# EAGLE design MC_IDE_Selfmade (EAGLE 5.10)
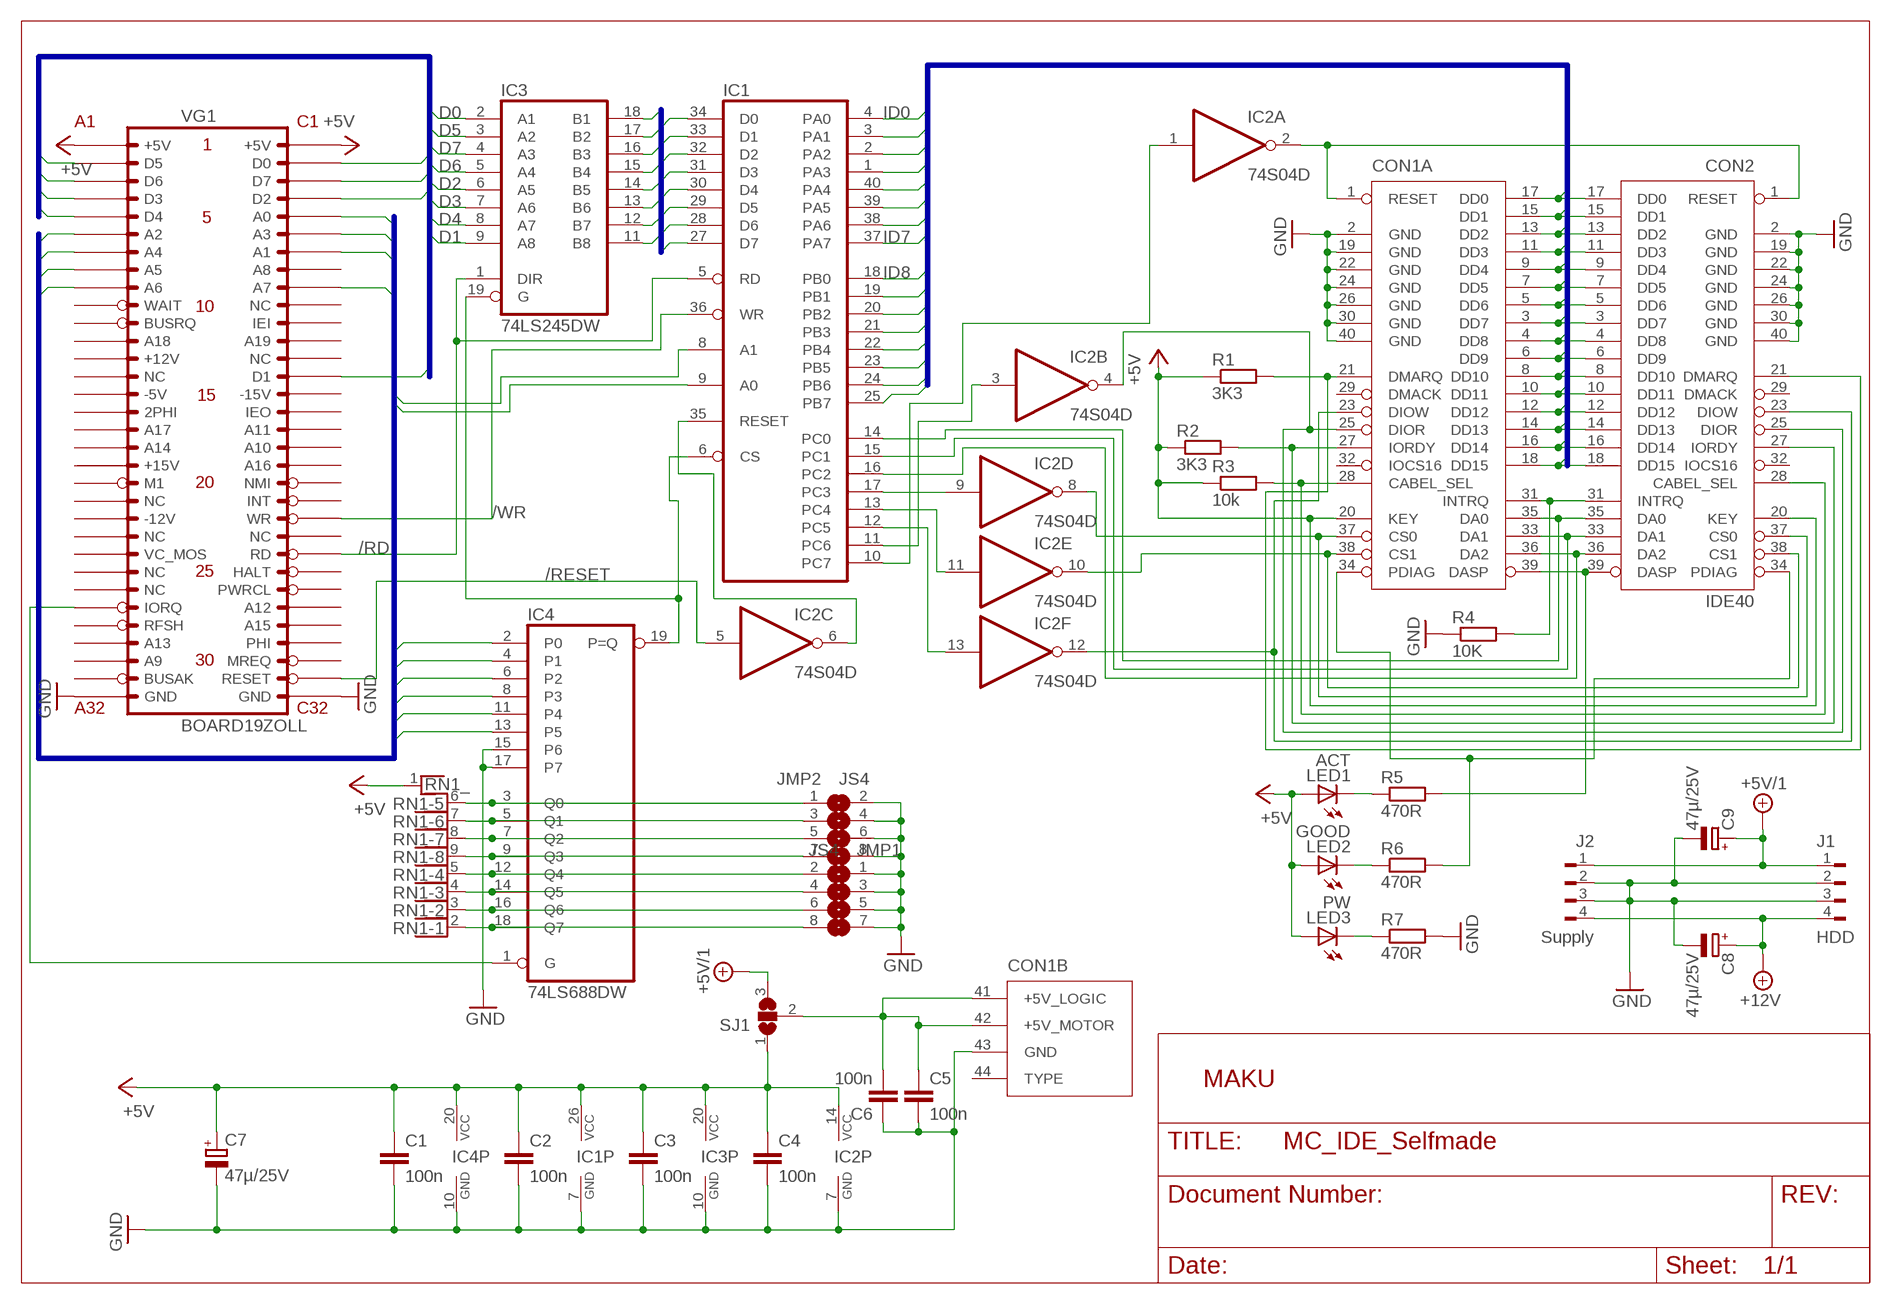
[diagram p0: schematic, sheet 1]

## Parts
C1  100n  C-EU050-025X075  [C050-025X075]
C2  100n  C-EU050-025X075  [C050-025X075]
C3  100n  C-EU050-025X075  [C050-025X075]
C4  100n  C-EU050-025X075  [C050-025X075]
C5  100n  C-EUC1210K  [C1210K]
C6  100n  C-EUC1210K  [C1210K]
C7  47µ/25V  CPOL-EUE2-5  [E2-5]
C8  47µ/25V  CPOL-EUE2-5  [E2-5]
C9  47µ/25V  CPOL-EUE2-5  [E2-5]
CON1  IDE_442,5"  [IDE_44]
CON2  IDE40  IDE_40  [ML40]
IC1  8255A  [DIL40]
IC2  74S04D  [SO14]
IC3  74LS245DW  [SO20W]
IC4  74LS688DW  [SO20W]
J1  HDD  FLOPPY-4350211  [350211]
J2  Supply  FLOPPY-4350211  [350211]
JMP1  JS4  [SJ4]
JMP2  JS4  [SJ4]
LED1  ACT  LED3MM  [LED3MM]
LED2  GOOD  LED3MM  [LED3MM]
LED3  PW  LED3MM  [LED3MM]
R1  3K3  R-EU_0207/10  [0207/10]
R2  3K3  R-EU_0207/10  [0207/10]
R3  10k  R-EU_0207/10  [0207/10]
R4  10K  R-EU_0207/10  [0207/10]
R5  470R  R-EU_0207/10  [0207/10]
R6  470R  R-EU_0207/10  [0207/10]
R7  470R  R-EU_0207/10  [0207/10]
RN1  RNX8  [RN-9]
SJ1  SJ2W  [SJ_2]
VG1  BOARD19ZOLL  [BOARD19S]

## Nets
+5V: C1.1 C2.1 C3.1 C4.1 C7.+ CON1.20(A:KEY) CON2.20(KEY) IC1.26(VCC) IC2.14(P:VCC) IC3.20(VCC) IC4.20(VCC) LED1.A LED2.A LED3.A R1.1 R2.1 R3.1 RN1.1 SJ1.1 VG1.A1(+5V) VG1.C1(+5V)
+5V/1: C9.+ J1.1 J2.1 SJ1.3
+12V: C8.+ J1.4 J2.4
/RD: IC1.5(RD) IC3.1(DIR) VG1.C24(RD)
/RESET: IC2.5(C:I) VG1.C31(RESET)
/WR: IC1.36(WR) VG1.C22(WR)
A0: IC1.9(A0) VG1.C5(A0)
A1: IC1.8(A1) VG1.C7(A1)
A2: IC4.2(P0) VG1.A6(A2)
A3: IC4.4(P1) VG1.C6(A3)
A4: IC4.6(P2) VG1.A7(A4)
A5: IC4.8(P3) VG1.A8(A5)
A6: IC4.11(P4) VG1.A9(A6)
A7: IC4.13(P5) VG1.C9(A7)
D0: IC3.2(A1) VG1.C2(D0)
D1: IC3.9(A8) VG1.C14(D1)
D2: IC3.6(A5) VG1.C4(D2)
D3: IC3.7(A6) VG1.A4(D3)
D4: IC3.8(A7) VG1.A5(D4)
D5: IC3.3(A2) VG1.A2(D5)
D6: IC3.5(A4) VG1.A3(D6)
D7: IC3.4(A3) VG1.C3(D7)
GND: C1.2 C2.2 C3.2 C4.2 C5.2 C6.1 C7.- C8.- C9.- CON1.2(A:GND) CON1.19(A:GND) CON1.22(A:GND) CON1.24(A:GND) CON1.26(A:GND) CON1.30(A:GND) CON1.40(A:GND) CON1.43(B:GND) CON2.2(GND) CON2.19(GND) CON2.22(GND) CON2.24(GND) CON2.26(GND) CON2.30(GND) CON2.40(GND) IC1.7(GND) IC2.7(P:GND) IC3.10(GND) IC4.10(GND) IC4.15(P6) IC4.17(P7) J1.2 J1.3 J2.2 J2.3 JMP1.1 JMP1.3 JMP1.5 JMP1.7 JMP2.2 JMP2.4 JMP2.6 JMP2.8 R4.1 R7.2 VG1.A32(GND) VG1.C32(GND)
ID0: CON1.17(A:DD0) CON2.17(DD0) IC1.4(PA0)
ID1: CON1.15(A:DD1) CON2.15(DD1) IC1.3(PA1)
ID2: CON1.13(A:DD2) CON2.13(DD2) IC1.2(PA2)
ID3: CON1.11(A:DD3) CON2.11(DD3) IC1.1(PA3)
ID4: CON1.9(A:DD4) CON2.9(DD4) IC1.40(PA4)
ID5: CON1.7(A:DD5) CON2.7(DD5) IC1.39(PA5)
ID6: CON1.5(A:DD6) CON2.5(DD6) IC1.38(PA6)
ID7: CON1.3(A:DD7) CON2.3(DD7) IC1.37(PA7)
ID8: CON1.4(A:DD8) CON2.4(DD8) IC1.18(PB0)
ID9: CON1.6(A:DD9) CON2.6(DD9) IC1.19(PB1)
ID10: CON1.8(A:DD10) CON2.8(DD10) IC1.20(PB2)
ID11: CON1.10(A:DD11) CON2.10(DD11) IC1.21(PB3)
ID12: CON1.12(A:DD12) CON2.12(DD12) IC1.22(PB4)
ID13: CON1.14(A:DD13) CON2.14(DD13) IC1.23(PB5)
ID14: CON1.16(A:DD14) CON2.16(DD14) IC1.24(PB6)
ID15: CON1.18(A:DD15) CON2.18(DD15) IC1.25(PB7)
N$1: LED1.K(C) R5.1
N$2: IC4.18(Q7) JMP1.8 RN1.2
N$3: C5.1 C6.2 CON1.41(B:+5V_LOGIC) CON1.42(B:+5V_MOTOR) SJ1.2
N$4: IC4.16(Q6) JMP1.6 RN1.3
N$5: LED2.K(C) R6.1
N$6: LED3.K(C) R7.1
N$7: CON1.34(A:PDIAG) CON2.34(PDIAG) R6.2
N$8: IC4.1(G) VG1.A27(IORQ)
N$9: IC4.14(Q5) JMP1.4 RN1.4
N$10: IC4.12(Q4) JMP1.2 RN1.5
N$11: IC4.3(Q0) JMP2.1 RN1.6
N$12: IC4.5(Q1) JMP2.3 RN1.7
N$14: IC4.7(Q2) JMP2.5 RN1.8
N$15: IC4.9(Q3) JMP2.7 RN1.9
N$17: CON1.31(A:INTRQ) CON2.31(INTRQ) R4.2
N$18: CON1.33(A:DA1) CON2.33(DA1) IC1.15(PC1)
N$19: CON1.35(A:DA0) CON2.35(DA0) IC1.14(PC0)
N$20: CON1.36(A:DA2) CON2.36(DA2) IC1.16(PC2)
N$21: CON1.39(A:DASP) CON2.39(DASP) R5.2
N$22: CON1.1(A:RESET) CON2.1(RESET) IC2.2(A:O)
N$25: CON1.21(A:DMARQ) CON2.21(DMARQ) R1.2
N$26: CON1.27(A:IORDY) CON2.27(IORDY) R2.2
N$27: CON1.28(A:CABEL_SEL) CON2.28(CABEL_SEL) R3.2
N$28: IC1.35(RESET) IC2.6(C:O)
N$29: IC1.17(PC3) IC2.9(D:I)
N$30: IC1.13(PC4) IC2.11(E:I)
N$31: CON1.25(A:DIOR) CON2.25(DIOR) IC2.4(B:O)
N$32: CON1.23(A:DIOW) CON2.23(DIOW) IC2.12(F:O)
N$33: IC1.12(PC5) IC2.13(F:I)
N$34: IC1.11(PC6) IC2.3(B:I)
N$35: CON1.38(A:CS1) CON2.38(CS1) IC2.10(E:O)
N$36: CON1.37(A:CS0) CON2.37(CS0) IC2.8(D:O)
N$37: IC1.10(PC7) IC2.1(A:I)
N$47: IC1.6(CS) IC3.19(G) IC4.19(P=Q)
QD0: IC1.34(D0) IC3.18(B1)
QD1: IC1.33(D1) IC3.11(B8)
QD2: IC1.32(D2) IC3.14(B5)
QD3: IC1.31(D3) IC3.13(B6)
QD4: IC1.30(D4) IC3.12(B7)
QD5: IC1.29(D5) IC3.17(B2)
QD6: IC1.28(D6) IC3.15(B4)
QD7: IC1.27(D7) IC3.16(B3)
Unconnected: CON1.29(A:DMACK) CON1.32(A:IOCS16) CON1.44(B:TYPE) CON2.29(DMACK) CON2.32(IOCS16) VG1.A10(WAIT) VG1.A12(A18) VG1.A13(+12V) VG1.A14(NC) VG1.A15(-5V) VG1.A16(2PHI) VG1.A17 VG1.A18(A14) VG1.A19(+15V) VG1.A21(NC) VG1.A22(-12V) VG1.A23(NC) VG1.A24(VC_MOS) VG1.A25(NC) VG1.A26(NC) VG1.A28(RFSH) VG1.C8(A8) VG1.C10(NC) VG1.C12(A19) VG1.C13(NC) VG1.C15(-15V) VG1.C16(IEO) VG1.C17(A11) VG1.C18(A10) VG1.C19(A16) VG1.C21(INT) VG1.C23(NC) VG1.C25(HALT) VG1.C26(PWRCL) VG1.C27(A12) VG1.C28(A15)

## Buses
IDE:ID[0..15]
EDATA:D[0..7]
EADD:A[0..19]
COV:QD[0..7]

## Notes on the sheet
- MAKU

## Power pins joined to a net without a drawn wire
A9: VG1.A30(A9)
A13: VG1.A29(A13)
BUSAK: VG1.A31(BUSAK)
BUSRQ: VG1.A11(BUSRQ)
IEI: VG1.C11(IEI)
M1: VG1.A20(M1)
MREQ: VG1.C30(MREQ)
NMI: VG1.C20(NMI)
PHI: VG1.C29(PHI)

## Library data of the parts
C1-C6 = rcl:C-EU: CAPACITOR, European symbol
C7-C9 = rcl:CPOL-EU: POLARIZED CAPACITOR, European symbol
CON1 = IDE_Drives:IDE_44
CON2 = IDE_Drives:IDE_40
IC1 = micro-intel:8255A: MICROCOMPUTER/PERIPHERAL DEVICE
IC2 = 74xx-eu:74*04: Hex INVERTER
IC3 = 74xx-eu:74*245: Octal BUS TRANSCEIVER, 3-state
IC4 = 74xx-eu:74*688: 8-bit MAGNITUDE/IDENTITY COMPARATOR, totem pole
J1 J2 = con-amp:FLOPPY-4: MATE N-LOCK Floppy / HDD conector Distributor: Bürklin 71F970
JMP1 JMP2 = jumper:JS4
LED1-LED3 = led-BigPad:LED: LED
R1-R7 = rcl:R-EU_: RESISTOR, European symbol
RN1 = resistor-net:RNX8: RESISTOR NETWORK
SJ1 = jumper:SJ2W: SMD solder JUMPER
VG1 = ThTec:BOARD19ZOLL

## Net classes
0 Default: width 0.8 mm, drill 0.6 mm, clearance 0.4 mm

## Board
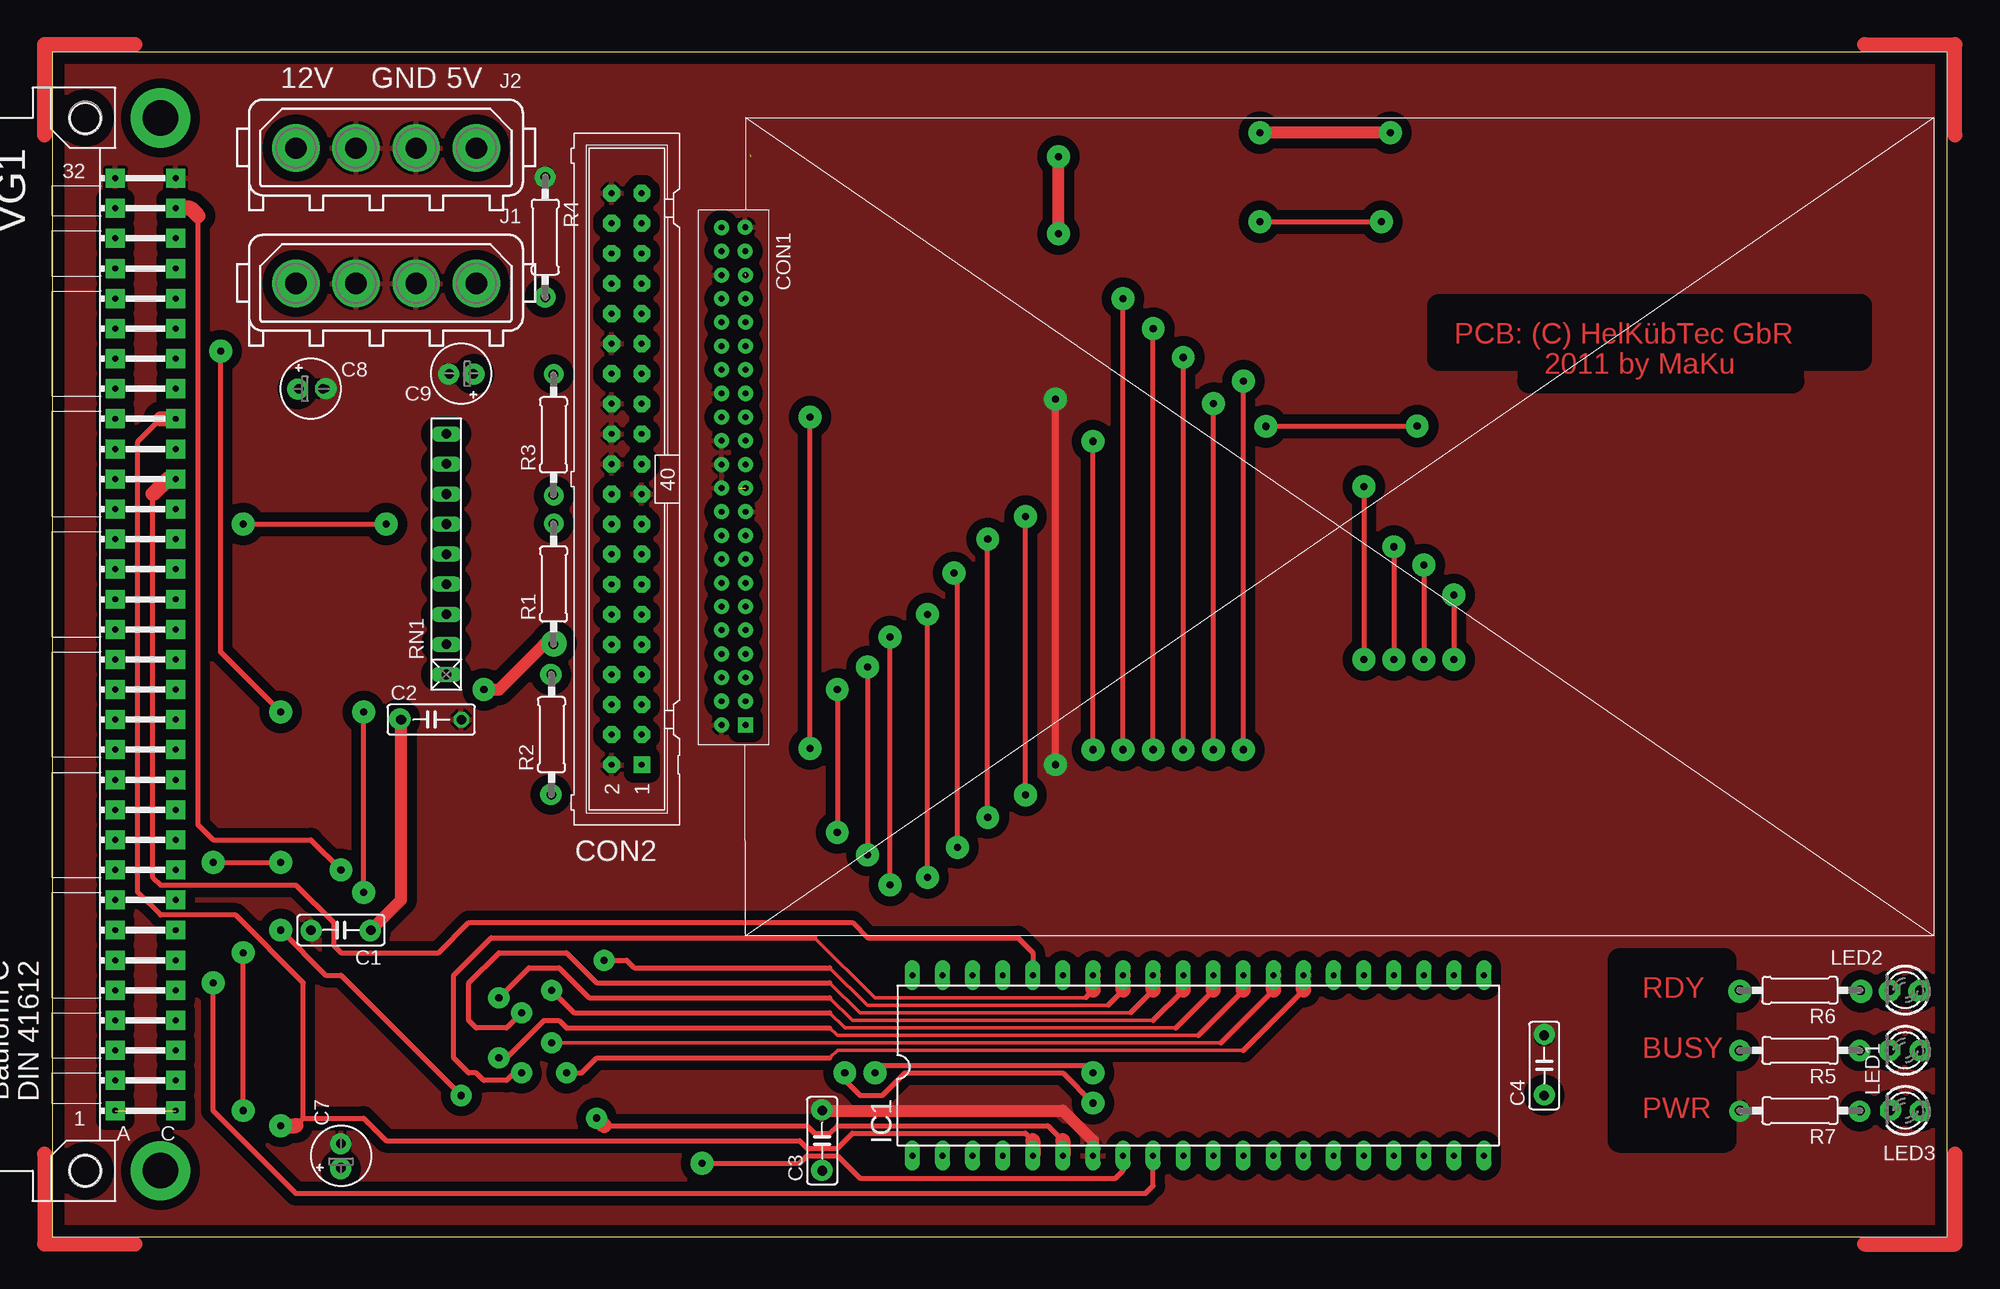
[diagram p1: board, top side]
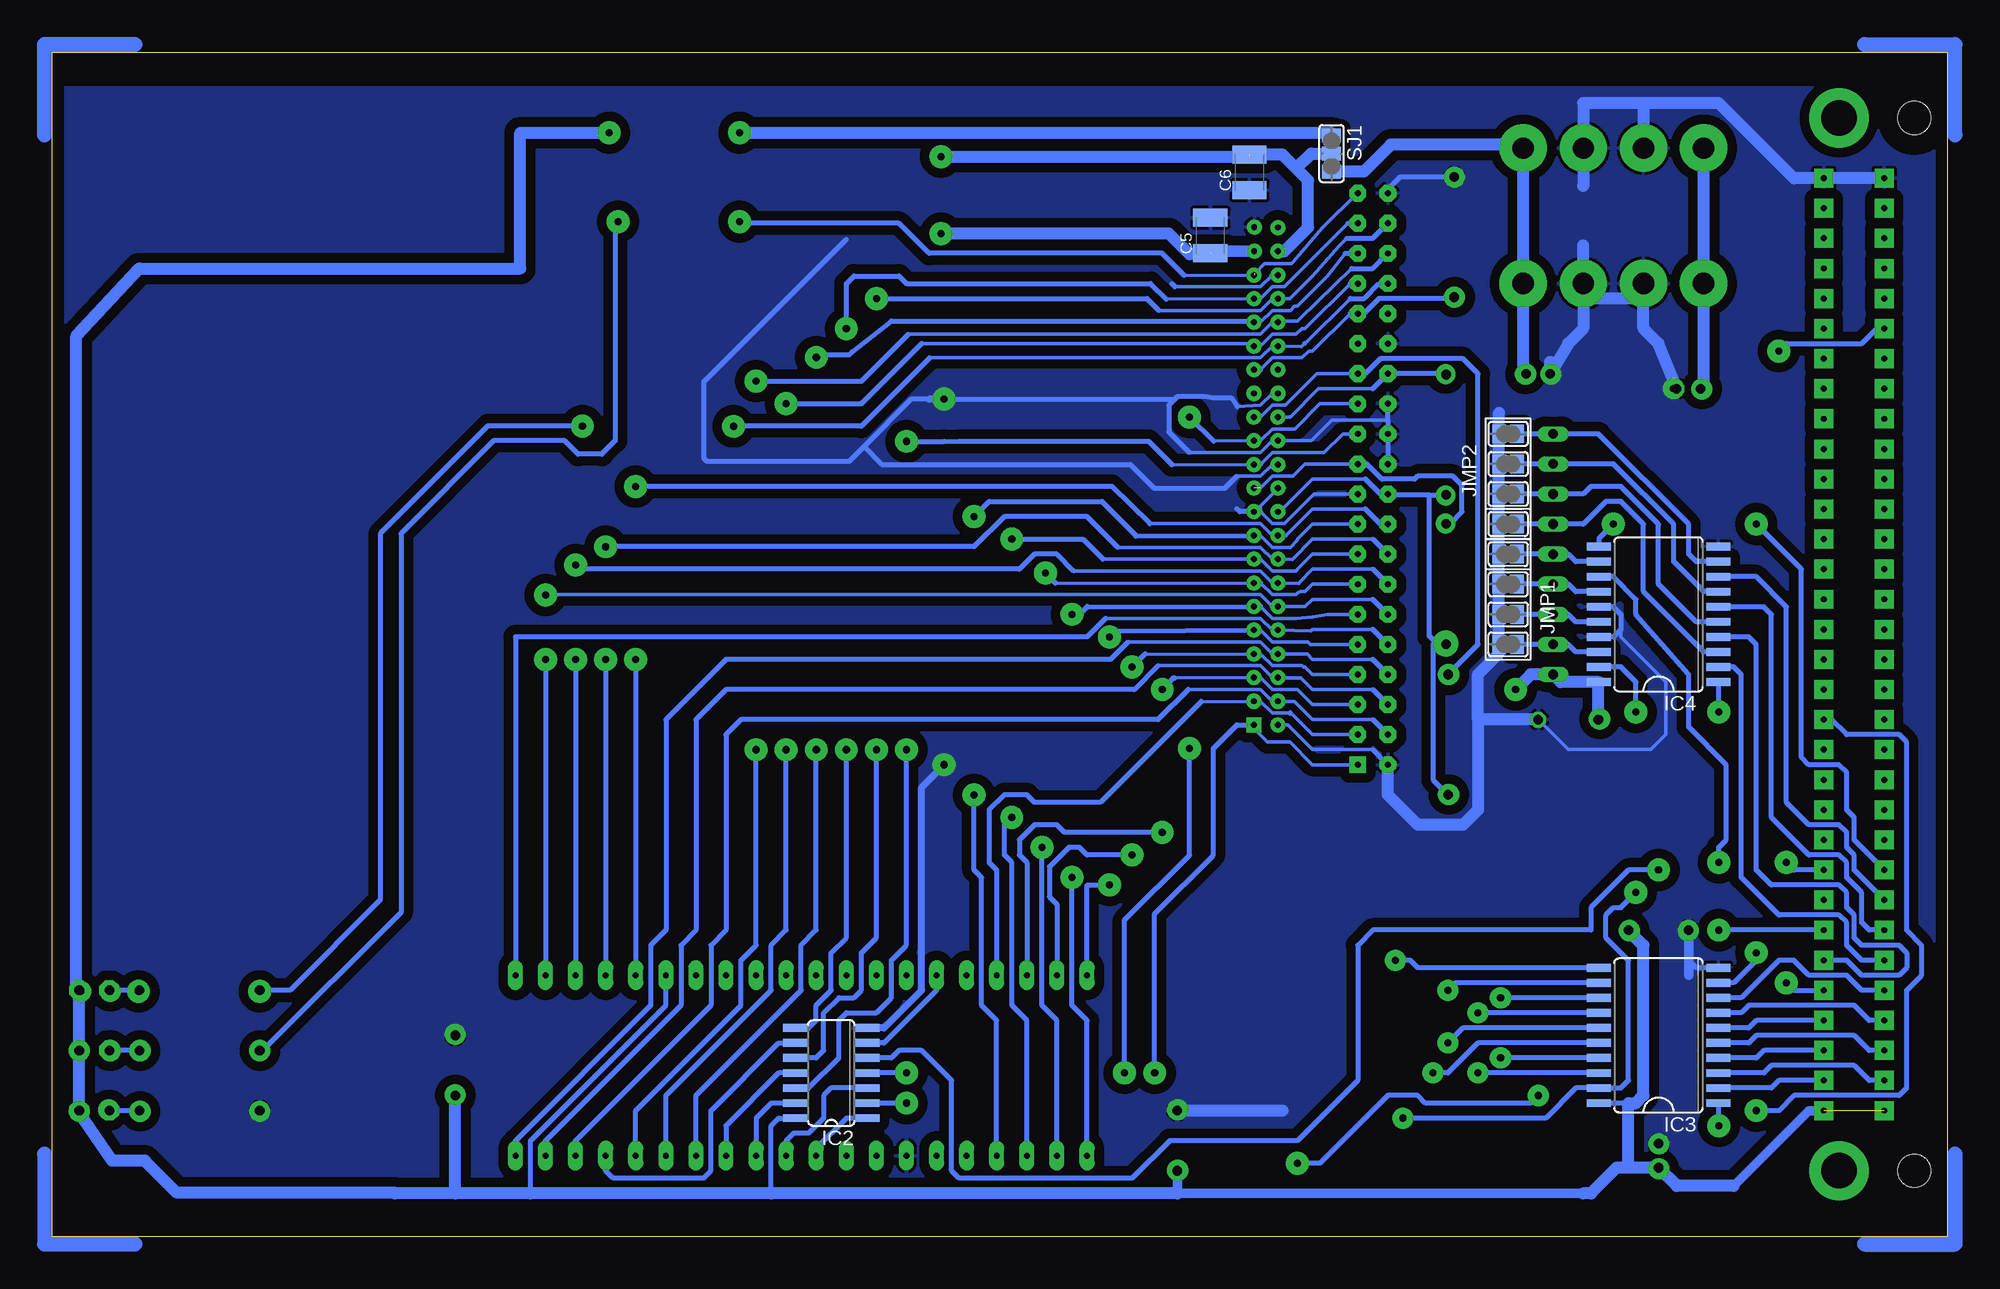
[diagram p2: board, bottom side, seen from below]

Size 160.02 x 100.03 mm. Coordinates in mm from the lower left corner, seen from the top.
Copper layers (1*16): Top 0.035mm / dielectric 1.5mm / Bottom 0.035mm
Design rules "default": minimum track width 10mil, minimum drill 24mil, track to track 8mil, track to pad 8mil, pad to pad 8mil, via to via 8mil, smd to smd 8mil, copper to edge 40mil, drill to drill 8mil, minimum pad ring 10mil, minimum via ring 8mil, stop-mask expansion 4mil, vias tented up to drill 0mil, thermal gap 10mil
tRestrict: 12 lines

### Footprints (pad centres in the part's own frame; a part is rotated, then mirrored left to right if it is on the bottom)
C050-025X075 = drill 0.813 octagon: 1 -2.54,0; 2 2.54,0
C1210K = smd 1.5 x 2.9: 1 -1.5,0; 2 1.5,0
E2-5 = drill 0.813 pad 1.27 round: + -1.016,0 | drill 0.813 pad 1.27 octagon: - 1.016,0
IDE_44 = drill 0.5 pad 1.27 square: 1 20,0 | drill 0.5 pad 1.27 round: 2 20,-2; 3 18,0; 4 18,-2; 5 16,0; 6 16,-2; 7 14,0; 8 14,-2; 9 12,0; 10 12,-2; 11 10,0; 12 10,-2; 13 8,0; 14 8,-2; 15 6,0; 16 6,-2; 17 4,0; 18 4,-2; 19 2,0; 20 2,-2; 21 0,0; 22 0,-2; 23 -2,0; 24 -2,-2; 25 -4,0; 26 -4,-2; 27 -6,0; 28 -6,-2; 29 -8,0; 30 -8,-2; 31 -10,0; 32 -10,-2; 33 -12,0; 34 -12,-2; 35 -14,0; 36 -14,-2; 37 -16,0; 38 -16,-2; 39 -18,0; 40 -18,-2; 41 -20.01,-0.01; 42 -20.01,-2.01; 43 -22.02,-0.01; 44 -22.01,-2.01
ML40 = drill 0.5 pad 1.422 square: 1 -24.13,-1.27 | drill 0.5 pad 1.422 octagon: 2 -24.13,1.27; 3 -21.59,-1.27; 4 -21.59,1.27; 5 -19.05,-1.27; 6 -19.05,1.27; 7 -16.51,-1.27; 8 -16.51,1.27; 9 -13.97,-1.27; 10 -13.97,1.27; 11 -11.43,-1.27; 12 -11.43,1.27; 13 -8.89,-1.27; 14 -8.89,1.27; 15 -6.35,-1.27; 16 -6.35,1.27; 17 -3.81,-1.27; 18 -3.81,1.27; 19 -1.27,-1.27; 20 -1.27,1.27; 21 1.27,-1.27; 22 1.27,1.27; 23 3.81,-1.27; 24 3.81,1.27; 25 6.35,-1.27; 26 6.35,1.27; 27 8.89,-1.27; 28 8.89,1.27; 29 11.43,-1.27; 30 11.43,1.27; 31 13.97,-1.27; 32 13.97,1.27; 33 16.51,-1.27; 34 16.51,1.27; 35 19.05,-1.27; 36 19.05,1.27; 37 21.59,-1.27; 38 21.59,1.27; 39 24.13,-1.27; 40 24.13,1.27
DIL40 = drill 0.5 pad 1.27 long: 1 -24.13,-7.62; 2 -21.59,-7.62; 3 -19.05,-7.62; 4 -16.51,-7.62; 5 -13.97,-7.62; 6 -11.43,-7.62; 7 -8.89,-7.62; 8 -6.35,-7.62; 9 -3.81,-7.62; 10 -1.27,-7.62; 11 1.27,-7.62; 12 3.81,-7.62; 13 6.35,-7.62; 14 8.89,-7.62; 15 11.43,-7.62; 16 13.97,-7.62; 17 16.51,-7.62; 18 19.05,-7.62; 19 21.59,-7.62; 20 24.13,-7.62; 21 24.13,7.62; 22 21.59,7.62; 23 19.05,7.62; 24 16.51,7.62; 25 13.97,7.62; 26 11.43,7.62; 27 8.89,7.62; 28 6.35,7.62; 29 3.81,7.62; 30 1.27,7.62; 31 -1.27,7.62; 32 -3.81,7.62; 33 -6.35,7.62; 34 -8.89,7.62; 35 -11.43,7.62; 36 -13.97,7.62; 37 -16.51,7.62; 38 -19.05,7.62; 39 -21.59,7.62; 40 -24.13,7.62
SO14 = smd 0.66 x 2.032: 1 -3.81,-3.073; 2 -2.54,-3.073; 3 -1.27,-3.073; 4 0,-3.073; 5 1.27,-3.073; 6 2.54,-3.073; 7 3.81,-3.073; 8 3.81,3.073; 9 2.54,3.073; 10 1.27,3.073; 11 0,3.073; 12 -1.27,3.073; 13 -2.54,3.073; 14 -3.81,3.073
SO20W = smd 0.66 x 2.032: 1 -5.715,-5.029; 2 -4.445,-5.029; 3 -3.175,-5.029; 4 -1.905,-5.029; 5 -0.635,-5.029; 6 0.635,-5.029; 7 1.905,-5.029; 8 3.175,-5.029; 9 4.445,-5.029; 10 5.715,-5.029; 11 5.715,5.029; 12 4.445,5.029; 13 3.175,5.029; 14 1.905,5.029; 15 0.635,5.029; 16 -0.635,5.029; 17 -1.905,5.029; 18 -3.175,5.029; 19 -4.445,5.029; 20 -5.715,5.029
350211 = drill 1.8 pad 4 round: 1 -7.62,0; 2 -2.54,0; 3 2.54,0; 4 7.62,0
SJ4 = smd 1.168 x 1.6: 1 -0.762,3.81; 2 0.762,3.81; 3 -0.762,1.27; 4 0.762,1.27; 5 -0.762,-1.27; 6 0.762,-1.27; 7 -0.762,-3.81; 8 0.762,-3.81
LED3MM = drill 0.813 pad 1.676 octagon: A -1.27,0; K 1.27,0
0207/10 = drill 0.813 octagon: 1 -5.08,0; 2 5.08,0
RN-9 = drill 0.813 long: 1 -10.16,0; 2 -7.62,0; 3 -5.08,0; 4 -2.54,0; 5 0,0; 6 2.54,0; 7 5.08,0; 8 7.62,0; 9 10.16,0
SJ_2 = smd 1.168 x 1.6: 1 -1.524,0; 2 0,0; 3 1.524,0
BOARD19S = drill 0.5 pad 1.6 square: A1 -3.81,5.08; A2 -3.81,7.62; A3 -3.81,10.16; A4 -3.81,12.7; A5 -3.81,15.24; A6 -3.81,17.78; A7 -3.81,20.32; A8 -3.81,22.86; A9 -3.81,25.4; A10 -3.81,27.94; A11 -3.81,30.48; A12 -3.81,33.02; A13 -3.81,35.56; A14 -3.81,38.1; A15 -3.81,40.64; A16 -3.81,43.18; A17 -3.81,45.72; A18 -3.81,48.26; A19 -3.81,50.8; A20 -3.81,53.34; A21 -3.81,55.88; A22 -3.81,58.42; A23 -3.81,60.96; A24 -3.81,63.5; A25 -3.81,66.04; A26 -3.81,68.58; A27 -3.81,71.12; A28 -3.81,73.66; A29 -3.81,76.2; A30 -3.81,78.74; A31 -3.81,81.28; A32 -3.81,83.82; C1 1.27,5.08; C2 1.27,7.62; C3 1.27,10.16; C4 1.27,12.7; C5 1.27,15.24; C6 1.27,17.78; C7 1.27,20.32; C8 1.27,22.86; C9 1.27,25.4; C10 1.27,27.94; C11 1.27,30.48; C12 1.27,33.02; C13 1.27,35.56; C14 1.27,38.1; C15 1.27,40.64; C16 1.27,43.18; C17 1.27,45.72; C18 1.27,48.26; C19 1.27,50.8; C20 1.27,53.34; C21 1.27,55.88; C22 1.27,58.42; C23 1.27,60.96; C24 1.27,63.5; C25 1.27,66.04; C26 1.27,68.58; C27 1.27,71.12; C28 1.27,73.66; C29 1.27,76.2; C30 1.27,78.74; C31 1.27,81.28; C32 1.27,83.82 | drill 3 pad 5 round: P$3 0,0; P$4 0,88.9 | hole 2.794: -6.35,0; -6.35,88.9

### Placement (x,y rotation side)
C1  24.38,25.88 180 top
C2  32,43.66 0 top
C3  65.02,8.1 90 top
C4  125.98,14.45 90 top
C5  62.23,84.55 90 bottom
C6  58.92,89.87 90 bottom
C7  24.38,6.83 90 top
C8  21.84,71.6 0 top
C9  34.54,72.87 180 top
CON1  58.53,63.21 270 top
CON2  48.51,63.98 90 top
IC1  96.77,14.45 0 top
IC2  94.23,13.82 90 bottom
IC3  24.38,16.99 90 bottom
IC4  24.38,52.55 90 bottom
J1  28.19,80.49 180 top
J2  28.19,91.92 180 top
JMP1  37.08,53.82 0 bottom
JMP2  37.08,63.98 180 bottom
LED1  156.46,15.72 180 top
LED2  156.46,20.8 180 top
LED3  156.46,10.64 180 top
R1  42.33,55.11 90 top
R2  42.16,42.39 90 top
R3  42.33,67.71 90 top
R4  41.63,84.41 270 top
R5  147.57,15.72 180 top
R6  147.57,20.8 180 top
R7  147.57,10.64 180 top
RN1  33.27,57.63 90 top
SJ1  51.99,91.46 270 bottom
VG1  9.14,5.56 0 top

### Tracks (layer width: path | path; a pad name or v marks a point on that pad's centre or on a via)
+5V  (via drill 0.6 pad 1.78, 0.6 pad 1.93)  (1 unrouted)
  Top 1.016: v36.45,46.2 37.72,46.2 41.53,50.01 42.31,50.01 R1.1 | C2.1 29.46,28.42 C1.1 | v112.98,93.21 v101.98,93.21
  Bottom 0.305: 56.13,61.44 53.59,63.98 49.15,63.98
  Bottom 0.406: IC2.14 98.68,10.01 99.31,9.37 99.31,3.66 | 49.15,63.98 47.88,62.71 CON2.20 47.16,62.63 43.73,62.63 | 43.73,62.63 R3.1 | R1.1 43.05,50.03 43.23,50.21 | 43.23,50.21 43.73,50.71 43.73,62.63 | R2.1 43.43,38.58 43.43,50.01 43.23,50.21 | 157.73,10.46 v157.73,10.59 LED3.A | 131.06,3.66 131.12,3.71 | 26.92,11.28 IC3.20 | IC1.26 108.2,19.53 119.63,8.1 119.63,3.66 | CON1.20 56.13,61.16 56.13,61.44
  Bottom 0.813: VG1.C1 11.68,10.64 18.03,4.29 | 30.73,3.66 65.02,3.66 C3.1
  Bottom 1.016: 65.02,3.66 99.31,3.66 119.63,3.66 125.98,3.66 | 125.98,3.66 131.06,3.66 | 26.92,5.82 C7.+ 22.86,4.29 18.03,4.29 | 26.92,5.82 27.94,5.82 30.1,3.66 30.73,3.66 | LED3.A v157.73,15.71 LED1.A LED2.A 157.98,21.05 157.98,76.05 152.65,81.76 120.5,81.76 120.5,93.21 v112.98,93.21 | 157.73,10.46 154.96,6.42 152.19,6.42 149.48,3.71 131.12,3.71 | C2.1 29.46,46.79 IC4.20 32.64,46.84 RN1.1 35.18,47.47 v36.45,46.2 | C1.1 25.65,24.61 25.65,11.91 26.29,11.28 26.92,11.28 26.92,5.82 | 125.98,3.66 C4.1 | SJ1.1 51.99,93.2 51.98,93.21 v101.98,93.21
+5V/1
  Bottom 1.016: C9.+ 35.81,73.13 J1.1 J2.1 36.1,92.21 46.98,92.21 49.26,89.94 SJ1.3
+12V
  Bottom 1.016: J2.4 J1.4 20.57,71.86 C8.+
/RD  (via drill 0.6 pad 1.93)
  Top 0.406: 20.57,9.37 21.21,10.01 | 21.21,10.01 21.21,21.44 15.49,27.15 9.14,27.15 7.24,29.06 7.24,67.16 9.14,69.06 | 82.8,8.1 82.17,8.74 67.56,8.74 66.29,7.47 63.75,7.47 63.12,8.1 28.19,8.1 26.29,10.01 21.21,10.01
  Top 1.27: v19.3,9.37 20.57,9.37 | 9.14,69.06 VG1.C24 | 82.8,8.1 IC1.5
  Bottom 0.406: IC3.1 19.35,9.42 v19.3,9.37
/RESET  (via drill 0.6 pad 1.93)
  Top 0.406: v24.38,30.96 21.84,33.5 13.59,33.5 12.32,34.77 12.32,86.21
  Top 1.27: 12.32,86.21 11.68,86.84 VG1.C31
  Bottom 0.406: IC2.5 89.15,15.09 88.52,15.72 86.61,15.72 84.07,13.18 84.07,5.56 83.44,4.93 68.83,4.93 65.66,8.1 54.86,8.1 49.78,13.18 49.78,24.61 48.51,25.88 30.1,25.88 30.1,27.79 26.92,30.96 v24.38,30.96
/WR
  Top 0.406: 8.51,62.71 8.51,30.33 9.14,29.69 20.57,29.69 23.75,26.52 23.75,24.61 24.38,23.98 32.64,23.98 35.18,26.52 67.56,26.52 68.83,25.25 81.53,25.25 82.8,23.98 IC1.36
  Top 1.27: VG1.C22 9.78,63.98 8.51,62.71
A0  (via drill 0.6 pad 1.93)
  Top 0.406: v13.59,21.44 13.59,10.64 20.57,3.66 92.33,3.66 92.96,4.29 IC1.9
  Bottom 0.406: VG1.C5 12.95,20.8 v13.59,21.44
A1  (via drill 0.6 pad 1.78, 0.6 pad 1.93)
  Top 0.406: v19.3,25.88 23.11,22.07 24.38,22.07 v34.54,11.91 | IC1.8 90.42,5.56 89.79,4.93 68.2,4.93 66.29,6.83 63.75,6.83 63.12,6.2 v54.86,6.2
  Bottom 0.406: VG1.C7 v19.3,25.88 | v54.86,6.2 52.96,6.2 47.24,11.91 44.7,11.91 44.07,11.28 35.18,11.28 v34.54,11.91
A2
  Bottom 0.406: VG1.A6 7.24,23.34 8.51,24.61 8.51,26.52 9.14,27.15 14.22,27.15 17.4,30.33 17.4,47.47 18.03,48.11 IC4.2
A3
  Bottom 0.406: VG1.C6 8.51,23.34 7.24,22.07 4.06,22.07 3.43,22.71 3.43,23.98 4.06,24.61 7.24,24.61 7.87,25.25 7.87,27.15 8.51,27.79 8.51,29.06 9.14,29.69 14.86,29.69 16.13,30.96 16.13,50.01 16.76,50.65 IC4.4
A4
  Bottom 0.406: VG1.A7 6.6,25.88 7.24,26.52 7.24,29.06 8.51,30.33 8.51,31.6 9.14,32.23 11.68,32.23 14.86,35.41 14.86,52.55 15.49,53.19 IC4.6
A5
  Bottom 0.406: VG1.A8 7.87,30.96 7.87,32.23 8.51,32.87 8.51,34.14 9.14,34.77 11.68,34.77 13.59,36.68 13.59,53.19 16.13,55.73 IC4.8
A6  (via drill 0.6 pad 1.93)
  Top 0.406: v16.13,60.17 v28.19,60.17
  Bottom 0.406: VG1.A9 7.87,33.5 7.87,35.41 8.51,36.04 8.51,39.22 9.14,39.85 11.68,39.85 12.32,40.49 12.32,56.36 v16.13,60.17 | IC4.11 29.41,58.95 v28.19,60.17
A7  (via drill 0.6 pad 1.93)
  Top 0.406: v13.59,31.6 v19.3,31.6
  Bottom 0.406: VG1.C9 12.95,30.96 v13.59,31.6 | v19.3,31.6 19.3,32.87 18.67,33.5 18.67,39.85 21.84,43.03 21.84,47.47 26.29,52.55 26.29,53.82 28.19,55.73 IC4.13
D0
  Bottom 0.406: IC3.2 14.86,12.55 14.22,13.18 VG1.C2
D1  (via drill 0.6 pad 1.93)
  Top 0.406: v16.13,10.64 v16.13,23.98
  Bottom 0.406: VG1.C14 9.78,43.66 8.51,42.39 4.06,42.39 3.43,41.76 3.43,25.88 2.16,24.61 2.16,22.07 3.43,20.8 3.43,12.55 4.06,11.91 12.95,11.91 14.22,10.64 v16.13,10.64 | v16.13,23.98 16.13,23.34 18.03,21.44 IC3.9
D2
  Bottom 0.406: IC3.6 16.76,17.63 16.13,18.26 VG1.C4
D3
  Bottom 0.406: VG1.A4 6.6,18.26 7.87,19.53 16.76,19.53 17.4,18.9 IC3.7
D4
  Bottom 0.406: IC3.8 17.4,20.17 14.22,23.34 12.95,23.34 11.68,22.07 8.51,22.07 7.24,20.8 VG1.A5
D5
  Bottom 0.406: VG1.A2 6.6,13.18 7.87,14.45 14.86,14.45 15.49,13.82 IC3.3
D6
  Bottom 0.406: VG1.A3 6.6,15.72 7.87,16.99 16.13,16.99 16.76,16.36 IC3.5
D7
  Bottom 0.406: IC3.4 16.13,15.09 15.49,15.72 VG1.C3
GND  (via drill 0.6 pad 1.78, 0.6 pad 1.93)
  Top 0.61: v84.71,39.85 v84.71,70.71
  Top 1.016: C3.2 85.34,10.64 87.88,8.1 IC1.7
  Bottom 0.305: 48.51,41.12 53.59,41.12 55.66,43.19 56.58,43.19 | CON2.19 53.48,62.71 55.98,60.21 56.98,60.21 57.98,61.21 57.98,61.71 56.58,63.11 | 56.98,67.21 57.98,66.21 63.98,66.21 | 47.24,68.96 51.96,68.96 53.71,67.21 CON1.26 | 59.94,70.08 57.98,70.21 56.98,71.21 CON1.30 | 27.56,52.55 27.56,50.65 23.75,46.84 23.75,42.39 25.02,41.12 32,41.12 C2.2 | CON1.24 57.03,65.16 57.98,64.21 59.98,64.21 | 57.03,81.16 57.98,80.21 65.23,80.21
  Bottom 0.406: IC3.10 21.21,22.71 21.84,23.34 | CON2.2 48.51,41.12 | CON2.26 47.24,68.96 CON2.24 CON2.22 | CON2.40 47.24,88.45 46.23,89.46 41.66,89.46 R4.1 | 59.94,70.08 60.46,70.85 61.98,70.85 62.73,70.96 64.98,70.96 65.23,70.71 | 63.98,66.21 65.73,67.96 65.73,70.21 65.23,70.71 | 92.98,84.21 104.98,72.21 104.98,65.71 104.73,65.46 92.73,65.46 91.48,66.71 | 91.48,66.71 87.48,70.71 85.98,70.71 | v84.71,70.71 65.23,70.71 | IC4.15 28.19,53.19 27.56,52.55 27.56,51.28 28.19,50.65 IC4.17 | 56.58,43.19 CON1.2 | 57.98,61.21 CON1.19 59.73,61.21 59.98,61.46 | 56.58,63.11 CON1.22 | CON1.26 56.93,67.16 56.98,67.21 | CON1.40 57.03,81.16 | 65.23,80.21 65.48,80.46 | 59.98,64.21 60.98,63.21 66.98,63.21 68.98,65.21 89.98,65.21 91.48,66.71
  Bottom 0.61: 37.85,49.25 JMP1.7 | IC2.7 89.79,17.63 86.61,20.8 86.61,37.95 v84.71,39.85 | v84.71,70.71 85.98,70.71
  Bottom 0.813: C1.2 21.84,23.34 21.84,22.07
  Bottom 1.016: JMP1.7 JMP1.5 JMP1.3 JMP1.1 JMP2.2 JMP2.4 JMP2.6 JMP2.8 37.85,69.57 | 37.85,49.25 39.62,47.47 39.62,43.66 | C2.2 39.62,43.66 | 25.65,95.73 J2.3 | 25.65,95.73 19.3,95.73 12.95,89.38 VG1.C32 VG1.A32 | 25.65,95.73 30.73,95.73 J2.2 30.73,88.71 | 30.73,83.71 J1.2 30.73,79.22 | 25.65,79.22 J1.3 | 25.65,79.22 30.73,79.22 | C8.- 24.38,75.41 25.65,76.68 25.65,79.22 | 30.73,79.22 30.73,76.68 32,75.41 C9.- 33.53,73.89 | 56.13,10.64 C3.2 | CON2.2 47.24,37.31 44.7,34.77 40.89,34.77 39.62,36.04 39.62,43.66
  other vias: 41.61,89.46 25.65,91.92 30.73,91.92 25.65,80.49 30.73,80.49 21.86,25.84 24.36,7.84 64.98,10.71 125.98,17.09 142.48,10.59 33.48,72.84 23.11,71.6
  pour Bottom (isolate 0.813): 0.25,97 159,97 160.27,97 160.27,3.02 0.25,3.02
  pour Top (isolate 0.813): 0.25,102.08 161.54,102.08 161.54,-2.06 -2.29,-2.06 -2.29,-3.33 -3.56,-3.33 -3.56,102.08
ID0  (via drill 0.6 pad 1.93)
  Top 0.406: v82.17,37.31 v82.17,60.81
  Bottom 0.305: CON2.17 53.59,60.17 54.86,58.9 54.86,58.83 55.48,58.21 56.98,58.21 57.98,59.21 CON1.17
  Bottom 0.406: IC1.4 80.26,18.26 81.53,19.53 81.53,30.33 82.17,30.96 v82.17,37.31 | v82.17,60.81 80.9,62.08 71.37,62.08 68.51,59.21 68.51,59.16 CON1.17
ID1  (via drill 0.6 pad 1.93)
  Top 0.406: v78.99,35.41 v78.99,58.9
  Bottom 0.305: CON2.15 53.59,57.63 54.86,56.36 54.86,56.33 54.98,56.21 56.98,56.21 57.98,57.21 CON1.15 71.3,57.21
  Bottom 0.406: IC1.3 77.72,18.26 78.99,19.53 78.99,31.6 79.63,32.23 79.63,34.77 v78.99,35.41 | 71.3,57.21 72.99,58.9 v78.99,58.9
ID2  (via drill 0.6 pad 1.93)
  Top 0.406: v76.45,32.87 76.45,55.73 v76.14,56.05
  Bottom 0.305: CON2.13 53.59,55.09 54.23,54.46 54.61,54.46 54.86,54.33 54.98,54.21 56.98,54.21 57.98,55.21 | 75.3,55.16 CON1.13
  Bottom 0.406: IC1.2 75.18,18.26 76.45,19.53 v76.45,32.87 | v76.14,56.05 75.3,55.21 75.3,55.16 | CON1.13 57.98,55.16 57.98,55.21
ID3  (via drill 0.6 pad 1.93)
  Top 0.406: v73.91,30.33 v73.91,52.55
  Bottom 0.305: CON2.11 52.32,52.55 53.59,52.33 54.98,52.21 56.98,52.21 57.98,53.21
  Bottom 0.406: IC1.1 72.64,18.26 73.91,19.53 v73.91,30.33 | v73.91,52.55 73.28,52.55 72.62,53.21 72.57,53.16 CON1.11 57.98,53.21
ID4  (via drill 0.6 pad 1.93)
  Top 0.406: v70.74,29.69 v70.74,50.65
  Bottom 0.305: CON2.9 53.78,50.01 53.98,50.21 56.98,50.21 57.98,51.21 CON1.9
  Bottom 0.406: v70.74,50.65 70.17,51.21 70.12,51.16 CON1.9 | IC1.40 72.64,29.69 v70.74,29.69
ID5  (via drill 0.6 pad 1.93)
  Top 0.406: v68.83,48.11 v68.83,32.23
  Bottom 0.305: CON2.7 53.59,47.47 54.23,48.11 54.38,48.11 54.48,48.21 56.98,48.21 57.98,49.21 58.03,49.16 CON1.7 67.78,49.16
  Bottom 0.406: 67.73,49.21 67.78,49.16 v68.83,48.11 | v68.83,32.23 72.64,32.23 73.28,32.87 74.18,32.87 75.82,31.23 75.82,28.69 75.18,28.06 IC1.39
ID6  (via drill 0.6 pad 1.93)
  Top 0.406: v66.29,46.2 v66.29,34.14
  Bottom 0.305: CON2.5 53.59,44.93 54.87,46.21 56.98,46.21 57.98,47.21 CON1.5 65.23,47.16
  Bottom 0.406: v66.29,46.2 65.28,47.21 65.23,47.16 | v66.29,34.14 74.55,34.14 75.18,34.77 77.09,34.77 78.36,33.5 78.36,32.23 77.72,31.6 IC1.38
ID7
  Bottom 0.305: CON2.3 53.59,42.39 55.25,44.05 55.5,44.23 | 55.51,44.21 56.98,44.21 57.98,45.21 CON1.3 62.98,45.16
  Bottom 0.406: 55.48,44.21 55.5,44.23 55.51,44.21 | IC1.37 80.26,30.96 80.9,31.6 80.9,36.04 79.63,37.31 77.72,37.31 77.09,36.68 71.52,36.68 62.98,45.21 62.98,45.16
ID8
  Bottom 0.305: 48.51,43.66 53.59,43.66 55.12,45.19 56.58,45.19 | 56.98,45.21 57.98,46.21 64.09,46.21
  Bottom 0.406: CON2.4 48.51,43.66 | IC1.18 115.82,8.1 104.39,19.53 104.39,24.61 103.12,25.88 103.12,42.39 101.85,43.66 66.64,43.66 64.09,46.21 | 56.58,45.19 CON1.4 56.98,45.16 56.98,45.21
ID9
  Bottom 0.305: 48.51,46.2 53.59,46.2 54.58,47.19 56.58,47.19 | 56.98,47.21 57.98,48.21 66.63,48.21
  Bottom 0.406: CON2.6 48.51,46.2 | IC1.19 118.36,8.1 106.93,19.53 106.93,24.61 105.66,25.88 105.66,43.66 103.12,46.2 68.64,46.2 66.63,48.21 | 56.58,47.19 CON1.6 56.98,47.16 56.98,47.21
ID10
  Bottom 0.305: 48.51,48.74 53.59,48.74 54.04,49.19 56.58,49.19 | 56.98,49.21 57.98,50.21 69.17,50.21
  Bottom 0.406: CON2.8 48.51,48.74 | IC1.20 120.9,8.1 109.47,19.53 109.47,24.61 108.2,25.88 108.2,43.66 103.12,48.74 70.64,48.74 69.17,50.21 | 56.58,49.19 CON1.8 56.98,49.16 56.98,49.21
ID11
  Bottom 0.305: 48.51,51.28 53.59,51.28 53.75,51.19 53.75,51.16 CON1.10 | 56.98,51.21 57.98,52.21 71.08,52.21
  Bottom 0.406: IC1.21 120.9,50.65 72.64,50.65 71.08,52.21 | CON2.10 48.51,51.28 | CON1.10 56.98,51.21
ID12  (via drill 0.6 pad 1.93)
  Top 0.406: v118.36,54.17 v118.36,48.74
  Bottom 0.305: 48.51,53.82 53.59,53.82 54.22,53.19 56.58,53.19 | 56.98,53.21 57.98,54.21 118.32,54.21 | CON1.12 56.98,53.16
  Bottom 0.406: v118.36,48.74 IC1.22 | CON2.12 48.51,53.82 | 118.32,54.21 v118.36,54.17 | 56.58,53.19 CON1.12 | 56.98,53.16 56.98,53.21
ID13  (via drill 0.6 pad 1.93)
  Top 0.406: v115.82,56.71 v115.82,48.74
  Bottom 0.305: 48.51,56.36 53.59,56.36 54.76,55.19 54.76,55.16 CON1.14 | 56.98,55.21 57.98,56.21 73.76,56.21
  Bottom 0.406: v115.82,48.74 IC1.23 | CON2.14 48.51,56.36 | 73.76,56.21 75.18,57.63 77.09,57.63 78.36,56.36 115.47,56.36 v115.82,56.71 | CON1.14 56.98,55.21
ID14  (via drill 0.6 pad 1.93)
  Top 0.406: v113.28,58.25 v113.28,48.74
  Bottom 0.305: 48.51,58.9 53.59,58.9 55.3,57.19 55.3,57.16 CON1.16 | 56.98,57.21 57.98,58.21 70.05,58.21
  Bottom 0.406: v113.28,48.74 IC1.24 | CON2.16 48.51,58.9 | 70.05,58.21 72.64,60.81 79.63,60.81 82.17,58.27 113.27,58.27 v113.28,58.25 | CON1.16 56.98,57.21
ID15  (via drill 0.6 pad 1.93)
  Top 0.406: v110.74,63.35 v110.74,48.74
  Bottom 0.305: 56.98,59.21 57.98,60.21 67.33,60.21 | 49.15,61.44 53.59,61.44 55.84,59.19 55.84,59.16 CON1.18
  Bottom 0.406: v110.74,48.74 IC1.25 | v110.74,63.35 70.55,63.35 67.33,60.21 | 49.15,61.44 47.88,60.17 CON2.18 | CON1.18 56.98,59.21
N$1
  Bottom 0.406: R5.1 LED1.K
N$2
  Bottom 0.406: IC4.18 31.37,49.38 32,50.01 RN1.2 JMP1.8
N$3  (via drill 0.6 pad 1.93)  (2 unrouted)
  Top 1.016: v84.98,84.71 v84.98,91.21
  Bottom 1.016: C5.1 62.11,83.17 CON1.41 | C6.2 56.14,91.37 54.98,90.21 | 54.98,90.21 53.98,89.21 53.98,85.21 55.98,83.21 CON1.42 | SJ1.2 53.73,91.46 54.98,90.21 | v84.98,91.21 58.98,91.21 | 62.23,82.96 63.98,82.96 65.73,84.71 v84.98,84.71
N$4
  Bottom 0.406: JMP1.6 RN1.3 32,52.55 31.37,51.92 IC4.16
N$5
  Bottom 0.406: R6.1 LED2.K
N$6
  Bottom 0.406: R7.1 LED3.K
N$7  (via drill 0.6 pad 1.93)
  Top 0.406: v102.49,68.43 113.95,68.43 v115.25,68.46
  Bottom 0.305: 50.42,79.22 54.23,75.41 54.26,75.44 | 56.98,75.21 57.98,74.21 85.91,74.21 | CON1.34 54.53,75.16 54.26,75.44
  Bottom 0.406: 54.26,75.44 | 85.91,74.21 91.69,68.43 v102.49,68.43 | 50.42,79.22 49.22,79.22 47.98,80.46 47.27,80.46 CON2.34 | v115.25,68.46 123.23,68.46 132.32,59.37 132.33,28.42 139.94,20.81 R6.2 | CON1.34 56.98,75.21
N$8  (via drill 0.6 pad 1.93)
  Top 0.406: v14.22,74.78 14.22,49.38 v19.3,44.3
  Bottom 0.406: VG1.A27 5.97,76.68 7.24,75.41 13.59,75.41 v14.22,74.78 | v19.3,44.3 19.3,46.79 IC4.1
N$9
  Bottom 0.406: IC4.14 31.37,54.46 32,55.09 RN1.4 JMP1.4
N$10
  Bottom 0.406: IC4.12 31.37,57 32,57.63 RN1.5 JMP1.2
N$11
  Bottom 0.406: JMP2.1 RN1.6 30.73,60.17 28.83,62.08 27.56,62.08 25.65,60.17 25.65,54.46 20.57,49.38 IC4.3
N$12
  Bottom 0.406: JMP2.3 RN1.7 30.73,62.71 30.1,63.35 27.56,63.35 24.38,60.17 24.38,55.09 21.21,51.92 IC4.5
N$13  (via drill 0.6 pad 1.93)
  other vias: 142.48,20.71
N$14
  Bottom 0.406: JMP2.5 RN1.8 28.19,65.25 23.11,60.17 23.11,57 20.57,54.46 IC4.7
N$15
  Bottom 0.406: JMP2.7 RN1.9 29.46,67.79 21.84,60.17 21.84,57.63 21.21,57 IC4.9
N$16  (via drill 0.6 pad 1.93)
  other vias: 152.73,20.71
N$17
  Bottom 0.305: 50.42,77.95 53.59,74.78 53.92,74.78 54.48,74.21 56.98,74.21 57.98,73.21
  Bottom 0.406: 50.42,77.95 CON2.31 49.24,77.95 47.98,79.21 41.75,79.21 R4.2 | 57.98,73.21 CON1.31
N$18  (via drill 0.6 pad 1.93)
  Top 0.406: v98.04,41.12 v98.04,70.33
  Bottom 0.305: 50.42,80.49 54.23,76.68 54.51,76.68 54.98,76.21 56.98,76.21 57.98,75.21 CON1.33 | 86.61,75.41 58.7,75.41
  Bottom 0.406: 50.42,80.49 CON2.33 | IC1.15 108.2,11.91 99.31,20.8 99.31,24.61 98.04,25.88 v98.04,41.12 | v98.04,70.33 91.69,70.33 86.61,75.41 | CON1.33 58.58,75.29 58.7,75.41
N$19  (via drill 0.6 pad 1.93)
  Top 0.406: v95.5,41.12 v95.5,74.25
  Bottom 0.305: 50.82,83.03 52.32,81.13 54.86,78.59 55.11,78.59 55.48,78.21 56.98,78.21 57.98,77.21 CON1.35
  Bottom 0.406: 50.82,83.03 CON2.35 | IC1.14 105.66,11.91 96.77,20.8 96.77,24.61 95.5,25.88 v95.5,41.12 | v95.5,74.25 95.5,74.47 92.73,74.47 92.48,74.71 89.15,77.32 58.74,77.32 CON1.35
N$20  (via drill 0.6 pad 1.93)
  Top 0.406: v100.58,41.12 v100.58,72.24
  Bottom 0.305: 50.3,81.76 51.69,80.38 54.69,77.49 54.86,77.32 56.43,77.32 | 56.98,77.21 57.98,76.21 87.72,76.21
  Bottom 0.406: CON2.36 48.51,81.76 50.3,81.76 | IC1.16 110.74,10.64 101.85,19.53 101.85,23.34 100.58,24.61 v100.58,41.12 | v100.58,72.24 91.69,72.24 87.72,76.21 | 56.43,77.32 CON1.36 56.98,77.21
N$21  (via drill 0.6 pad 1.93)  (1 unrouted)
  Top 0.406: v101.98,85.71 v112.23,85.71
  Bottom 0.305: 58.48,81.32 57.65,82.15 55.38,82.15 55.25,82.28 52.75,85.19 49.82,88.11 | CON1.39 64.42,81.16
  Bottom 0.406: R5.2 142.22,15.72 130.57,27.37 130.57,59.37 122.73,67.21 116.75,67.21 115.62,66.08 113.62,66.08 112.48,67.21 112.48,85.46 v112.23,85.71 | v101.98,85.71 101.84,85.57 88.52,85.57 85.98,83.03 66.29,83.03 64.42,81.16 | 49.82,88.11 CON2.39
N$22  (via drill 0.6 pad 1.93)
  Top 0.406: v87.88,11.28 85.34,13.82 72.01,13.82 70.1,11.91 68.2,11.91 66.93,13.18 v66.93,13.82
  Bottom 0.305: 58.67,43.03 57.4,41.76 55.5,41.76 53.59,39.85 CON2.1
  Bottom 0.406: v87.88,11.28 IC2.2 | v66.93,13.82 66.93,27.27 61.98,32.21 61.98,41.21 59.98,43.21 CON1.1 58.58,43.03 58.67,43.03
N$23  (via drill 0.6)
  other vias: 33.27,67.79
N$24  (via drill 0.6)
  other vias: 33.27,65.25
N$25  (1 unrouted)
  Bottom 0.305: CON2.21 54.23,65.25 55.27,64.21 56.98,64.21 57.98,63.21
  Bottom 0.406: R1.2 42,60.19 40.98,61.21 40.98,63.46 41.73,64.21 44.73,64.21 44.98,63.96 47.73,63.96 49.02,65.25 CON2.21
N$26
  Bottom 0.305: CON2.27 53.23,72.87 55.89,70.21 56.98,70.21 57.98,69.21 CON1.27
  Bottom 0.406: R2.2 39.62,50.01 39.62,72.87 40.89,74.14 47.88,74.14 49.15,72.87 CON2.27
N$27
  Bottom 0.305: 48.51,71.6 53.09,71.6 55.48,69.21 CON1.28
  Bottom 0.406: 48.51,71.6 CON2.28 42.41,72.87 R3.2
N$28
  Bottom 0.406: IC1.35 85.34,20.8 89.79,16.36 IC2.6
N$29
  Bottom 0.406: IC2.9 98.68,16.36 104.39,10.64 104.39,5.56 105.03,4.93 112.65,4.93 113.28,5.56 IC1.17
N$30
  Bottom 0.406: IC2.11 98.68,13.82 103.12,9.37 IC1.13
N$31  (via drill 0.6 pad 1.93)
  Top 0.406: v87.88,13.82 87.25,14.45 69.47,14.45 v69.47,13.82 | v63.98,41.21 v63.98,69.21
  Bottom 0.305: CON2.25 52.96,70.33 55.08,68.21 56.98,68.21 57.98,67.21 CON1.25 61.93,67.16
  Bottom 0.406: v87.88,13.82 IC2.4 | v69.47,13.82 69.47,26.73 63.98,32.21 v63.98,41.21 | v63.98,69.21 61.93,67.16
N$32  (via drill 0.6 pad 1.93)
  Top 0.406: v87.88,41.12 v87.88,67.16
  Bottom 0.305: CON2.23 51.05,67.79 52.63,66.21 56.98,66.21 57.98,65.21 | 65.43,65.16 CON1.23
  Bottom 0.406: IC2.12 96.14,12.55 93.6,15.09 93.6,18.26 92.96,18.9 90.42,18.9 89.15,20.17 89.15,23.34 87.88,24.61 v87.88,41.12 | v87.88,67.16 84.71,67.16 83.42,67.17 67.44,67.17 65.43,65.16 | CON1.23 57.98,65.21
N$33
  Bottom 0.406: IC1.12 100.58,10.01 99.31,11.28 IC2.13
N$34
  Bottom 0.406: IC1.11 98.04,8.1 97.41,8.74 96.14,8.74 94.87,10.01 94.87,11.91 94.23,12.55 IC2.3
N$35  (via drill 0.6 pad 1.93)
  Top 0.406: v90.42,41.12 v90.42,79.22
  Bottom 0.305: 50.71,84.3 51.34,83.67 53.59,81.13 55.51,79.21 CON1.38 | 56.98,79.21 57.98,78.21 66.55,78.21
  Bottom 0.406: 50.71,84.3 48.51,84.3 CON2.38 | IC2.10 95.5,15.09 94.87,15.72 94.87,18.9 93.6,20.17 92.33,20.17 91.69,20.8 91.69,23.98 90.42,25.25 v90.42,41.12 | v90.42,79.22 67.56,79.22 66.55,78.21 | CON1.38 56.93,79.16 56.98,79.21
N$36  (via drill 0.6 pad 1.93)
  Top 0.406: v92.96,41.12 v92.96,76.68
  Bottom 0.305: 50.62,85.57 55.98,80.21 56.98,80.21 57.98,79.21 CON1.37 65.93,79.16
  Bottom 0.406: IC2.8 96.14,17.63 95.5,18.26 95.5,19.53 94.23,20.8 94.23,23.98 92.96,25.25 v92.96,41.12 | v92.96,76.68 92.96,80.49 92.33,81.13 88.52,81.13 87.88,80.49 67.26,80.49 65.93,79.16 | 50.62,85.57 CON2.37
N$37
  Bottom 0.406: IC1.10 95.5,7.47 92.96,10.01 IC2.1
N$38  (via drill 0.6)
  other vias: 33.27,62.71
N$39  (via drill 0.6)
  other vias: 33.27,60.17
N$40  (via drill 0.6)
  other vias: 33.27,57.63
N$41  (via drill 0.6)
  other vias: 33.27,55.09
N$42  (via drill 0.6)
  other vias: 33.27,52.55
N$43  (via drill 0.6)
  other vias: 33.27,50.01
N$44  (via drill 0.6)
  other vias: 33.27,47.47
N$45  (via drill 0.6 pad 1.68)
  other vias: 42.36,62.59
N$46  (via drill 0.6 pad 1.68)
  other vias: 42.36,72.84
N$47  (via drill 0.6 pad 1.78, 0.6 pad 1.93)
  Top 0.406: v26.29,29.06 v26.29,44.3 | 85.34,8.1 84.07,9.37 66.29,9.37 65.66,8.74 64.39,8.74 63.75,9.37 46.61,9.37
  Top 1.27: 85.34,8.1 IC1.6 | v45.97,10.01 46.61,9.37
  Bottom 0.406: v26.29,29.06 27.56,27.79 28.19,27.79 28.83,27.15 28.83,25.25 26.92,23.34 26.92,13.18 27.56,12.55 IC3.19 31.37,12.55 33.91,10.01 v45.97,10.01 | v26.29,44.3 26.29,46.84 27.56,48.11 IC4.19
N$48  (via drill 0.6 pad 1.68)
  other vias: 42.36,60.21
N$49  (via drill 0.6 pad 2.18)
  other vias: 42.36,50.09
N$50  (via drill 0.6 pad 1.78)
  other vias: 42.11,47.46
N$51  (via drill 0.6 pad 1.78)
  other vias: 42.11,37.34
N$52  (via drill 0.6 pad 1.78)
  other vias: 20.73,71.59
N$55  (via drill 0.6 pad 1.78)
  other vias: 35.61,72.84
N$56  (via drill 0.6 pad 1.78)
  other vias: 20.57,80.49
N$59  (via drill 0.6 pad 1.78)
  other vias: 35.81,80.49
N$60  (via drill 0.6 pad 1.78)
  other vias: 20.57,91.92
N$63  (via drill 0.6 pad 1.78)
  other vias: 35.81,91.92
N$65  (via drill 0.6 pad 1.78)
  other vias: 41.61,79.34
N$66  (via drill 0.6 pad 1.78)
  other vias: 142.48,15.71
N$67  (via drill 0.6 pad 1.78)
  other vias: 152.61,15.71
N$68  (via drill 0.6 pad 1.78)
  other vias: 155.11,20.71
N$69  (via drill 0.6 pad 1.78)
  other vias: 157.61,20.71
N$70  (via drill 0.6 pad 1.78)
  other vias: 155.11,15.71
N$71  (via drill 0.6 pad 1.78)
  other vias: 155.23,10.71
N$72  (via drill 0.6 pad 1.78)
  other vias: 152.61,10.59
N$74  (via drill 0.6 pad 1.78)
  other vias: 125.98,11.96
N$77  (via drill 0.6 pad 1.78)
  other vias: 64.98,5.59
N$78  (via drill 0.6 pad 1.78)
  other vias: 24.36,5.71
N$81  (via drill 0.6 pad 1.78)
  other vias: 26.86,25.84
N$82  (via drill 0.6 pad 1.78)
  other vias: 29.36,43.71
QD0  (via drill 0.6 pad 1.78)
  Top 0.305: 64.39,25.25 69.47,20.17 87.25,20.17
  Top 0.406: v39.62,13.82 38.99,13.82 38.35,13.18 36.45,13.18 35.81,13.82 35.18,13.82 33.91,15.09 33.91,22.07 37.08,25.25 64.39,25.25 | 87.25,20.17 87.88,20.8
  Top 1.27: 87.88,20.8 IC1.34
  Bottom 0.406: IC3.18 v39.62,13.82
QD1  (via drill 0.6 pad 1.78)
  Top 0.305: 89.15,19.53 68.83,19.53 65.66,22.71
  Top 0.406: 89.15,19.53 90.42,20.8 | v46.61,23.34 48.51,23.34 49.15,22.71 65.66,22.71
  Top 1.27: 90.42,20.8 IC1.33
  Bottom 0.406: IC3.11 44.7,22.71 45.34,23.34 v46.61,23.34
QD2  (via drill 0.6 pad 1.78)
  Top 0.305: 91.06,18.9 68.2,18.9 65.66,21.44
  Top 0.406: 91.06,18.9 92.96,20.8 | 65.66,21.44 45.97,21.44 43.43,23.98 37.72,23.98 35.18,21.44 35.18,18.26 35.81,17.63 38.35,17.63 v39.62,18.9
  Top 1.27: 92.96,20.8 IC1.32
  Bottom 0.406: IC3.14 v39.62,18.9
QD3  (via drill 0.6 pad 1.78)
  Top 0.305: 65.66,20.17 67.56,18.26 92.96,18.26
  Top 0.406: v37.72,20.17 40.26,22.71 42.8,22.71 45.34,20.17 65.66,20.17 | 92.96,18.26 95.5,20.8
  Top 1.27: 95.5,20.8 IC1.31
  Bottom 0.406: IC3.13 v37.72,20.17
QD4  (via drill 0.6 pad 1.78)
  Top 0.305: 65.66,18.9 66.93,17.63 94.87,17.63
  Top 0.406: v42.16,20.8 44.07,18.9 65.66,18.9 | 94.87,17.63 98.04,20.8
  Top 1.27: 98.04,20.8 IC1.30
  Bottom 0.406: IC3.12 41.53,21.44 v42.16,20.8
QD5  (via drill 0.6 pad 1.78)
  Top 0.305: 65.66,17.63 66.29,16.99 96.77,16.99
  Top 0.406: v37.72,15.09 38.35,15.09 41.53,18.26 42.8,18.26 43.43,17.63 65.66,17.63 | 96.77,16.99 100.58,20.8
  Top 1.27: 100.58,20.8 IC1.29
  Bottom 0.406: IC3.17 v37.72,15.09
QD6  (via drill 0.6 pad 1.78)
  Top 0.305: v42.16,16.36 98.68,16.36
  Top 0.406: 98.68,16.36 103.12,20.8
  Top 1.27: 103.12,20.8 IC1.28
  Bottom 0.406: IC3.15 40.89,17.63 v42.16,16.36
QD7  (via drill 0.6 pad 1.78)
  Top 0.305: 65.66,15.09 66.29,15.72 100.58,15.72
  Top 0.406: v43.43,13.82 44.7,13.82 45.97,15.09 65.66,15.09 | 100.58,15.72 105.66,20.8
  Top 1.27: 105.66,20.8 IC1.27
  Bottom 0.406: IC3.16 39.62,16.36 42.16,13.82 v43.43,13.82

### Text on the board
Top: PCB: (C) HelKübTec GbR | 2011 by MaKu | RDY | BUSY | PWR
tPlace: 12V | GND | 5V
